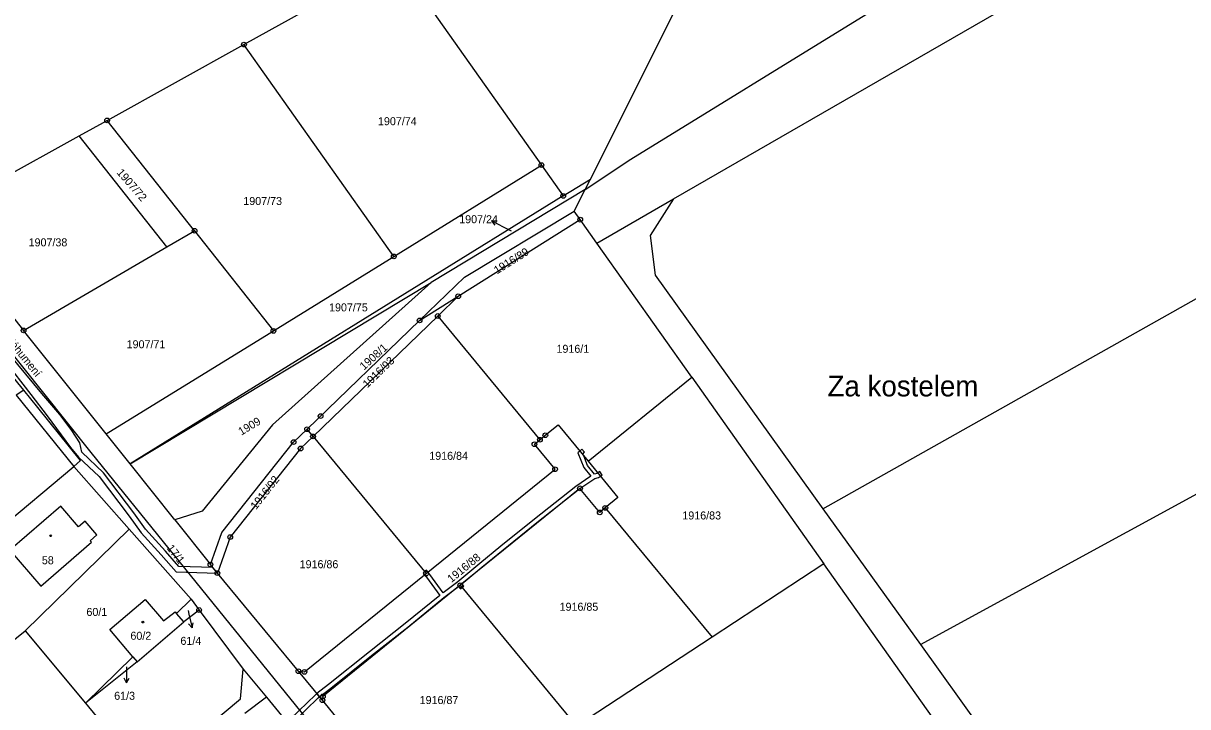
# Model space of a CAD drawing. Extents: x -504988 to -494607, y -1123820 to -1114018.
# Drawn here: x -497559.8 to -497312.5, y -1119375.9 to -1119230.8 of the extents above; entities that cross this region are included whole.
import ezdxf

# ---------------------------------------------------------------- set-up
doc = ezdxf.new("R2010")
doc.units = 0
for name, color, linetype in [('Hranice parcel', 7, 'Continuous'), ('Parcelní čísla', 7, 'Continuous'), ('Pop  PČ popisy', 7, 'Continuous'), ('Vnitřní kresba', 7, 'Continuous'), ('Věcná břemena k části', 7, 'Continuous'), ('Značky bodu BP', 7, 'Continuous'), ('Značky budov', 7, 'Continuous')]:
    doc.layers.add(name, color=color, linetype=linetype)

msp = doc.modelspace()

# ---------------------------------------------------------------- linework, layer by layer
at = {"layer": 'Hranice parcel'}
for p, q in [((-497439.3, -1119263.88), (-497392.25, -1119170.03)), ((-497478.71, -1119219.93), (-497449.7, -1119260.9)), ((-497512.88, -1119235.33), (-497497.43, -1119226.77)), ((-497541.94, -1119251.43), (-497512.88, -1119235.33)), ((-497481.06, -1119280.3), (-497512.88, -1119235.33)), ((-497547.89, -1119254.72), (-497541.94, -1119251.43)), ((-497523.38, -1119274.85), (-497541.94, -1119251.43)), ((-497578.93, -1119271.92), (-497547.89, -1119254.72)), ((-497529.25, -1119278.26), (-497547.89, -1119254.72)), ((-497481.06, -1119280.3), (-497449.7, -1119260.9)), ((-497449.7, -1119260.9), (-497445.07, -1119267.45)), ((-497445.07, -1119267.45), (-497439.3, -1119263.88)), ((-497440.42, -1119266.12), (-497439.3, -1119263.88)), ((-497445.07, -1119267.45), (-497537.07, -1119324.32)), ((-497440.42, -1119266.12), (-497473.13, -1119285.84)), ((-497442.73, -1119270.71), (-497440.42, -1119266.12)), ((-497437.94, -1119277.47), (-497421.66, -1119268.06)), ((-497578.93, -1119271.92), (-497559.68, -1119296.02)), ((-497467.38, -1119288.74), (-497441.47, -1119272.49)), ((-497466.07, -1119284.7), (-497442.73, -1119270.71)), ((-497441.47, -1119272.49), (-497442.73, -1119270.71)), ((-497437.94, -1119277.47), (-497441.47, -1119272.49)), ((-497529.25, -1119278.26), (-497523.38, -1119274.85)), ((-497523.38, -1119274.85), (-497506.62, -1119296.1)), ((-497417.77, -1119305.96), (-497437.94, -1119277.47)), ((-497559.68, -1119296.02), (-497529.25, -1119278.26)), ((-497506.62, -1119296.1), (-497481.06, -1119280.3)), ((-497475.58, -1119293.88), (-497466.07, -1119284.7)), ((-497537.07, -1119324.32), (-497473.13, -1119285.84)), ((-497475.58, -1119293.88), (-497467.38, -1119288.74)), ((-497467.38, -1119288.74), (-497471.74, -1119292.95)), ((-497499.49, -1119316.98), (-497475.58, -1119293.88)), ((-497471.74, -1119292.95), (-497498.22, -1119318.53)), ((-497471.74, -1119292.95), (-497450.03, -1119319.22)), ((-497542.13, -1119317.99), (-497559.68, -1119296.02)), ((-497542.13, -1119317.99), (-497506.62, -1119296.1)), ((-497439.81, -1119323.75), (-497417.77, -1119305.96)), ((-497417.77, -1119305.96), (-497389.7, -1119345.59)), ((-497561.3, -1119309.73), (-497549.05, -1119324.87)), ((-497498.22, -1119318.53), (-497499.49, -1119316.98)), ((-497537.07, -1119324.32), (-497542.13, -1119317.99)), ((-497498.22, -1119318.53), (-497474.2, -1119347.62)), ((-497527.58, -1119336.21), (-497537.07, -1119324.32)), ((-497572.13, -1119344.3), (-497549.05, -1119324.87)), ((-497549.05, -1119324.87), (-497537.28, -1119338.19)), ((-497436.14, -1119333.69), (-497413.46, -1119361.16)), ((-497389.92, -1119333.92), (-497369.23, -1119362.71)), ((-497527.58, -1119336.21), (-497520, -1119345.73)), ((-497559.35, -1119359.77), (-497537.28, -1119338.19)), ((-497537.28, -1119338.19), (-497524.12, -1119353.08)), ((-497515.8, -1119339.88), (-497518.52, -1119347.52)), ((-497518.52, -1119347.52), (-497520, -1119345.73)), ((-497389.7, -1119345.59), (-497413.46, -1119361.16)), ((-497362.83, -1119383.54), (-497389.7, -1119345.59)), ((-497501.31, -1119368.36), (-497518.52, -1119347.52)), ((-497500.03, -1119368.5), (-497474.2, -1119347.62)), ((-497466.94, -1119350.12), (-497496.13, -1119373.72)), ((-497466.94, -1119350.12), (-497442.25, -1119380.02)), ((-497527.21, -1119356.13), (-497524.12, -1119353.08)), ((-497524.12, -1119353.08), (-497522.41, -1119355.37)), ((-497525.68, -1119357.9), (-497527.21, -1119356.13)), ((-497522.41, -1119355.37), (-497525.68, -1119357.9)), ((-497522.41, -1119355.37), (-497513.05, -1119367.92)), ((-497535.6, -1119366.39), (-497525.68, -1119357.9)), ((-497567.14, -1119366.09), (-497559.35, -1119359.77)), ((-497559.35, -1119359.77), (-497546.51, -1119375.18)), ((-497413.46, -1119361.16), (-497442.25, -1119380.02)), ((-497546.51, -1119375.18), (-497536.51, -1119365.31)), ((-497535.6, -1119366.39), (-497546.51, -1119375.18)), ((-497536.51, -1119365.31), (-497535.6, -1119366.39)), ((-497501.31, -1119368.36), (-497500.03, -1119368.5)), ((-497496.13, -1119373.72), (-497496.22, -1119374.52)), ((-497546.51, -1119375.18), (-497533.57, -1119390.95)), ((-497474.33, -1119401.04), (-497496.22, -1119374.52))]:
    msp.add_line(p, q, dxfattribs=at)
for points in [[(-497440.42, -1119266.12), (-497430.74, -1119259.63), (-497380.78, -1119228.96), (-497271.05, -1119168.96), (-497129.83, -1119097.24), (-497024.69, -1119052.4), (-496985.19, -1119041.96), (-496953.46, -1119038.9), (-496840.51, -1119032.5), (-496642.35, -1119017.59), (-496506.08, -1119016.07), (-496344.6, -1119008.27), (-496165.15, -1119008.22), (-495985.71, -1119008.18), (-495806.26, -1119008.13)], [(-497421.66, -1119268.06), (-497305.5, -1119201.14), (-497137.57, -1119115.36), (-497020.03, -1119064.29), (-496998.33, -1119058.82), (-496967.32, -1119056.12), (-496935.98, -1119050.13), (-496827.78, -1119045.57), (-496641.58, -1119030.49), (-496521.56, -1119029.43)], [(-497389.92, -1119333.92), (-497273.96, -1119268.61), (-497130.48, -1119202.62), (-496968.1, -1119149.16), (-496865.39, -1119132.4), (-496762.67, -1119115.64), (-496613.16, -1119109.4)], [(-497369.23, -1119362.71), (-497260.22, -1119303.31), (-497116.11, -1119237.59), (-496957.81, -1119187.66), (-496857.35, -1119168.99), (-496756.89, -1119150.32), (-496613.61, -1119144.68)], [(-497421.66, -1119268.06), (-497426.65, -1119275.89), (-497425.58, -1119284.3), (-497389.92, -1119333.92)], [(-497473.13, -1119285.84), (-497506.83, -1119316.06), (-497521.76, -1119334.39), (-497527.58, -1119336.21)], [(-497520, -1119345.73), (-497517.57, -1119338.9), (-497502.34, -1119319.73), (-497499.49, -1119316.98)], [(-497450.03, -1119319.22), (-497448.88, -1119318.27), (-497446.18, -1119316.04), (-497439.81, -1119323.75)], [(-497498.22, -1119318.53), (-497500.86, -1119321.08), (-497515.8, -1119339.88)], [(-497474.2, -1119347.62), (-497446.82, -1119325.47), (-497451.19, -1119320.18), (-497450.03, -1119319.22)], [(-497439.81, -1119323.75), (-497433.45, -1119331.46), (-497436.14, -1119333.69)], [(-497436.14, -1119333.69), (-497437.31, -1119334.64), (-497441.52, -1119329.54), (-497466.94, -1119350.12)], [(-497562.61, -1119342.64), (-497556.04, -1119350.28), (-497545.24, -1119340.99), (-497545.53, -1119340.65), (-497544.13, -1119339.44), (-497546.64, -1119336.52), (-497548.04, -1119337.73), (-497551.81, -1119333.35), (-497562.61, -1119342.64)], [(-497536.51, -1119365.31), (-497541.39, -1119359.51), (-497533.9, -1119353.13), (-497529.95, -1119357.7), (-497527.53, -1119355.76), (-497527.21, -1119356.13)], [(-497369.23, -1119362.71), (-497356.53, -1119380.38), (-497345.47, -1119411.41)], [(-497533.57, -1119390.95), (-497513.6, -1119374.26), (-497513.05, -1119367.92)], [(-497513.05, -1119367.92), (-497508.11, -1119373.91), (-497505.55, -1119377.01), (-497500.92, -1119382.63)], [(-497496.22, -1119374.52), (-497499.62, -1119370.4), (-497501.31, -1119368.36)]]:
    msp.add_lwpolyline(points, dxfattribs=at)
at = {"layer": 'Pop  PČ popisy'}
for p, q in [((-497457.63, -1119274.14), (-497460.28, -1119272.73)), ((-497460.28, -1119272.73), (-497459.16, -1119272.76)), ((-497460.28, -1119272.73), (-497459.63, -1119273.64)), ((-497456.1, -1119274.94), (-497457.63, -1119274.14)), ((-497524.77, -1119355.51), (-497524.6, -1119356.27)), ((-497524.6, -1119356.27), (-497523.92, -1119359.19)), ((-497523.92, -1119359.19), (-497524.64, -1119358.33)), ((-497523.92, -1119359.19), (-497523.66, -1119358.11)), ((-497537.8, -1119367.41), (-497537.8, -1119367.83)), ((-497537.8, -1119367.83), (-497537.8, -1119370.83)), ((-497537.8, -1119370.83), (-497538.3, -1119369.83)), ((-497537.8, -1119370.83), (-497537.3, -1119369.83))]:
    msp.add_line(p, q, dxfattribs=at)
at = {"layer": 'Vnitřní kresba'}
for p, q in [((-497585.74, -1119271.57), (-497545.39, -1119321.91)), ((-497559.66, -1119308.7), (-497562.5, -1119305.22)), ((-497559.66, -1119308.7), (-497561.3, -1119309.73)), ((-497556.64, -1119312.39), (-497559.66, -1119308.7)), ((-497547.57, -1119323.63), (-497556.64, -1119312.39)), ((-497545.39, -1119321.91), (-497457.24, -1119430.73)), ((-497549.05, -1119324.87), (-497547.57, -1119323.63)), ((-497508.11, -1119373.91), (-497512.71, -1119377.33))]:
    msp.add_line(p, q, dxfattribs=at)
at = {"layer": 'Věcná břemena k části'}
msp.add_lwpolyline([(-497563.71, -1119302.43), (-497558.17, -1119309.58), (-497554.68, -1119314.15), (-497549.74, -1119320.85), (-497548.01, -1119322.92), (-497543.63, -1119327.04), (-497537.25, -1119335.43), (-497534.72, -1119338.99), (-497530.46, -1119343.68), (-497527.26, -1119347.29), (-497518.48, -1119347.57), (-497519.5, -1119346.34), (-497526.7, -1119346.11), (-497529.56, -1119342.88), (-497533.78, -1119338.23), (-497536.29, -1119334.71), (-497542.73, -1119326.24), (-497547.35, -1119321.89), (-497547.73, -1119319.91), (-497549.43, -1119317.24), (-497551.97, -1119313.85), (-497555.83, -1119309.43), (-497562.64, -1119301.22)], dxfattribs=at)
for points in [[(-497496.82, -1119373.8), (-497494.42, -1119371.94), (-497485.77, -1119365.02), (-497478.08, -1119358.98), (-497470.44, -1119352.74), (-497467.29, -1119350.4), (-497466.93, -1119350.87), (-497466.56, -1119350.58), (-497466.22, -1119350.32), (-497466.59, -1119349.83), (-497462.36, -1119346.31), (-497457.83, -1119342.56), (-497450.65, -1119336.76), (-497441.52, -1119329.54), (-497438.4, -1119327.43), (-497437.59, -1119327.25), (-497437.16, -1119326.97), (-497436.81, -1119326.74), (-497437.3, -1119325.99), (-497437.73, -1119326.27), (-497437.95, -1119326.41), (-497438.41, -1119326.51), (-497439.94, -1119324.66), (-497440.72, -1119322.65), (-497440.99, -1119322.32), (-497440.53, -1119321.87), (-497441.16, -1119321.22), (-497441.57, -1119321.62), (-497441.95, -1119321.98), (-497440.72, -1119325.12), (-497439.24, -1119326.92), (-497442.41, -1119329.12), (-497451.21, -1119336.05), (-497458.33, -1119341.81), (-497462.78, -1119345.51), (-497467.48, -1119349.4), (-497470.58, -1119351.72), (-497473.4, -1119347.85), (-497473.81, -1119347.3), (-497474.1, -1119346.91), (-497474.52, -1119347.23), (-497474.82, -1119347.45), (-497474.51, -1119347.87), (-497474.11, -1119348.4), (-497471.29, -1119352.27), (-497478.62, -1119358.26), (-497486.25, -1119364.25), (-497494.9, -1119371.17), (-497497.39, -1119373.11)], [(-497497.39, -1119373.11), (-497497.71, -1119373.36), (-497503.01, -1119378.47), (-497503.87, -1119379.05), (-497504.91, -1119379.76), (-497505.23, -1119380.44), (-497504.41, -1119380.82), (-497504.18, -1119380.34), (-497503.3, -1119379.74), (-497502.39, -1119379.13), (-497497.12, -1119374.03), (-497496.82, -1119373.8)]]:
    msp.add_lwpolyline(points, close=True, dxfattribs=at)
at = {"layer": 'Značky bodu BP'}
for centre, radius in [((-497512.88, -1119235.33), 0.5), ((-497512.88, -1119235.33), 0.0303), ((-497541.94, -1119251.43), 0.5), ((-497541.94, -1119251.43), 0.0303), ((-497449.7, -1119260.9), 0.5), ((-497449.7, -1119260.9), 0.0303), ((-497445.07, -1119267.45), 0.5), ((-497445.07, -1119267.45), 0.0303), ((-497441.47, -1119272.49), 0.5), ((-497441.47, -1119272.49), 0.0303), ((-497523.38, -1119274.85), 0.5), ((-497523.38, -1119274.85), 0.0303), ((-497481.06, -1119280.3), 0.5), ((-497481.06, -1119280.3), 0.0303), ((-497467.38, -1119288.74), 0.5), ((-497467.38, -1119288.74), 0.0303), ((-497475.58, -1119293.88), 0.5), ((-497475.58, -1119293.88), 0.0303), ((-497471.74, -1119292.95), 0.5), ((-497471.74, -1119292.95), 0.0303), ((-497559.68, -1119296.02), 0.5), ((-497559.68, -1119296.02), 0.0303), ((-497506.62, -1119296.1), 0.5), ((-497506.62, -1119296.1), 0.0303), ((-497496.61, -1119314.2), 0.5), ((-497496.61, -1119314.2), 0.0303), ((-497499.49, -1119316.98), 0.5), ((-497499.49, -1119316.98), 0.0303), ((-497502.34, -1119319.73), 0.5), ((-497498.22, -1119318.53), 0.5), ((-497498.22, -1119318.53), 0.0303), ((-497450.03, -1119319.22), 0.5), ((-497450.03, -1119319.22), 0.0303), ((-497448.88, -1119318.27), 0.5), ((-497448.88, -1119318.27), 0.0303), ((-497502.34, -1119319.73), 0.0303), ((-497500.86, -1119321.08), 0.5), ((-497500.86, -1119321.08), 0.0303), ((-497451.19, -1119320.18), 0.5), ((-497451.19, -1119320.18), 0.0303), ((-497446.82, -1119325.47), 0.5), ((-497446.82, -1119325.47), 0.0303), ((-497441.52, -1119329.54), 0.5), ((-497441.52, -1119329.54), 0.0303), ((-497437.31, -1119334.64), 0.5), ((-497436.14, -1119333.69), 0.5), ((-497436.14, -1119333.69), 0.0303), ((-497437.31, -1119334.64), 0.0303), ((-497515.8, -1119339.88), 0.5), ((-497515.8, -1119339.88), 0.0303), ((-497520, -1119345.73), 0.5), ((-497520, -1119345.73), 0.0303), ((-497518.52, -1119347.52), 0.5), ((-497518.52, -1119347.52), 0.0303), ((-497474.2, -1119347.62), 0.5), ((-497474.2, -1119347.62), 0.0303), ((-497466.94, -1119350.12), 0.5), ((-497466.94, -1119350.12), 0.0303), ((-497522.41, -1119355.37), 0.5), ((-497522.41, -1119355.37), 0.0303), ((-497501.31, -1119368.36), 0.5), ((-497501.31, -1119368.36), 0.0303), ((-497500.03, -1119368.5), 0.5), ((-497500.03, -1119368.5), 0.0303), ((-497496.13, -1119373.72), 0.5), ((-497496.13, -1119373.72), 0.0303), ((-497496.22, -1119374.52), 0.5), ((-497496.22, -1119374.52), 0.0303)]:
    msp.add_circle(centre, radius, dxfattribs=at)
at = {"layer": 'Značky budov'}
for centre in [(-497553.93, -1119339.61), (-497534.36, -1119357.94)]:
    msp.add_circle(centre, 0.175, dxfattribs=at)

# ---------------------------------------------------------------- texts
at = {"layer": 'Parcelní čísla'}
for s, p in [('1907/74', (-497484.42, -1119252.44)), ('1907/73', (-497513.02, -1119269.38)), ('1907/24', (-497467.17, -1119273.25)), ('1907/38', (-497558.62, -1119278.16)), ('1907/75', (-497494.81, -1119291.97)), ('1907/71', (-497537.8, -1119299.8)), ('1916/1', (-497446.51, -1119300.76)), ('1916/84', (-497473.53, -1119323.48)), ('1916/83', (-497419.78, -1119336.15)), ('58', (-497555.81, -1119345.66)), ('1916/86', (-497501.06, -1119346.5)), ('1916/85', (-497445.85, -1119355.53)), ('60/1', (-497546.34, -1119356.63)), ('60/2', (-497537, -1119361.69)), ('61/4', (-497526.38, -1119362.77)), ('61/3', (-497540.45, -1119374.43)), ('1916/87', (-497475.57, -1119375.34))]:
    msp.add_text(s, height=1.7, dxfattribs=at).set_placement(p)
for s, rotation, p in [('1907/72', 311, (-497540.02, -1119262.57)), ('1916/89', 32, (-497459.15, -1119284.13)), ('1908/1', 42, (-497487.39, -1119304.54)), ('1916/93', 44, (-497486.69, -1119308.33)), ('1909', 31, (-497513.46, -1119318.37)), ('1916/92', 52, (-497510.31, -1119334.17)), ('17/1', 308, (-497529.39, -1119342.27)), ('1916/88', 39, (-497468.84, -1119349.67))]:
    msp.add_text(s, height=1.7, rotation=rotation, dxfattribs=at).set_placement(p)
at = {"layer": 'Pop  PČ popisy'}
msp.add_text('Záhumení', height=1.7, rotation=309, dxfattribs=at).set_placement((-497563.49, -1119298.1))
msp.add_text('Za kostelem', height=4.4, dxfattribs=at).set_placement((-497388.95, -1119310.02))

doc.saveas('drawing.dxf')
